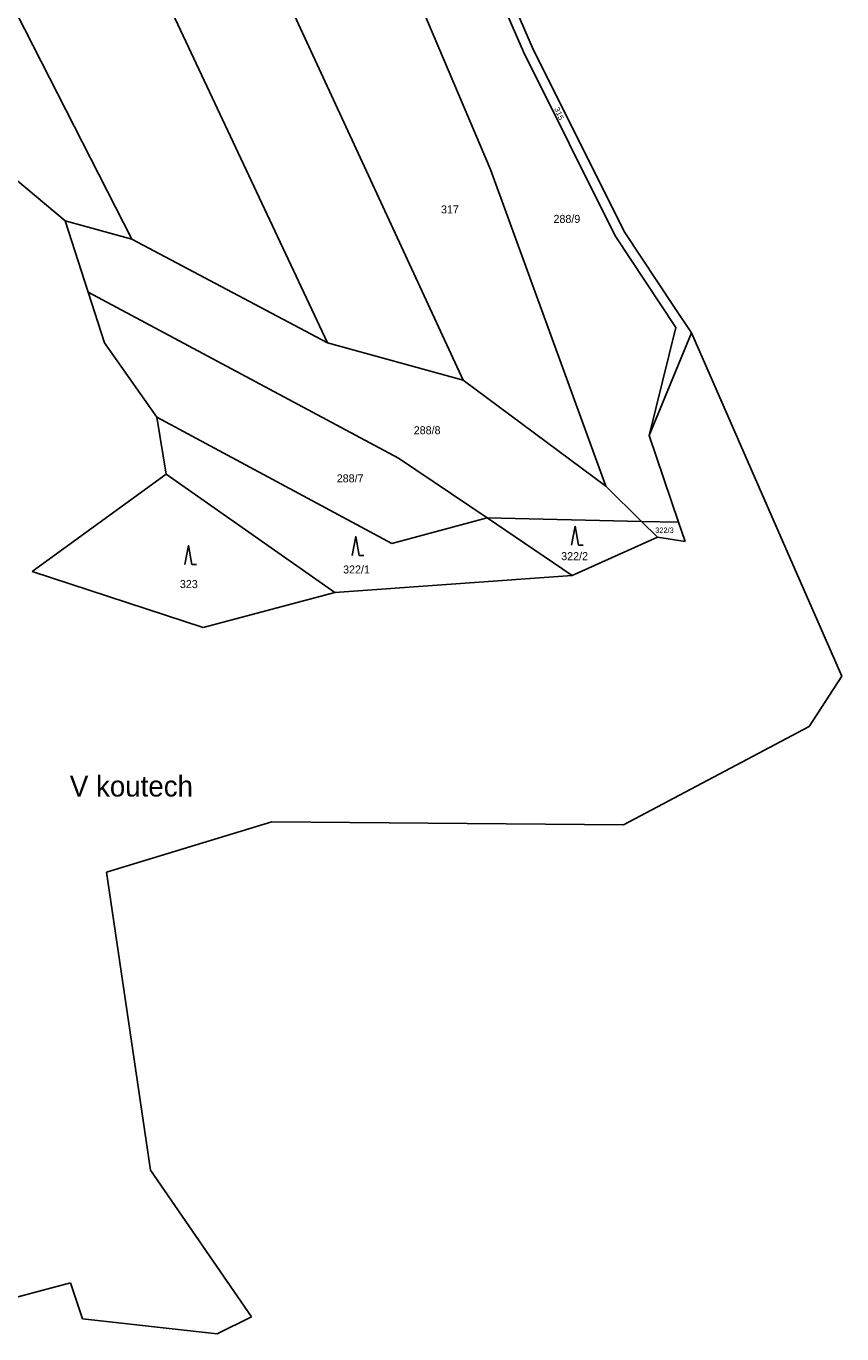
# Model space of a CAD drawing. Extents: x -664548 to -662415, y -1069720 to -1068208.
# Drawn here: x -662952.7 to -662779.3, y -1069462.9 to -1069185.2 of the extents above; entities that cross this region are included whole.
import ezdxf
from ezdxf.enums import TextEntityAlignment as Align

# ---------------------------------------------------------------- set-up
doc = ezdxf.new("R2010")
doc.units = 0
doc.header["$LTSCALE"] = 0.68
for name, color, linetype, lineweight in [('1', 7, 'Continuous', 25), ('3', 7, 'Continuous', 25), ('7', 7, 'Continuous', 13)]:
    doc.layers.add(name, color=color, linetype=linetype, lineweight=lineweight)
doc.layers.add('2', color=7, linetype='Continuous')

msp = doc.modelspace()

# ---------------------------------------------------------------- linework, layer by layer
at = {"layer": '1'}
for p, q in [((-662888.64, -1069252.46), (-662947.44, -1069127.48)), ((-662854.01, -1069215.69), (-662875.68, -1069164.53)), ((-662847.01, -1069190.67), (-662858.78, -1069163.55)), ((-662930.23, -1069230.45), (-662960.45, -1069171.24)), ((-662897.41, -1069179.04), (-662859.82, -1069260.43)), ((-662845.08, -1069189.83), (-662825.61, -1069228.81)), ((-662827.49, -1069229.75), (-662847.01, -1069190.67)), ((-662944.39, -1069226.53), (-662971.11, -1069204.3)), ((-662829.48, -1069282.94), (-662854.01, -1069215.69)), ((-662944.39, -1069226.53), (-662930.23, -1069230.45)), ((-662939.52, -1069241.68), (-662944.39, -1069226.53)), ((-662825.61, -1069228.81), (-662814.9, -1069244.97)), ((-662930.23, -1069230.45), (-662888.64, -1069252.46)), ((-662814.61, -1069249.19), (-662827.49, -1069229.75)), ((-662936.05, -1069252.46), (-662939.52, -1069241.68)), ((-662873.54, -1069276.97), (-662939.52, -1069241.68)), ((-662814.9, -1069244.97), (-662811.32, -1069250.37)), ((-662820.32, -1069272.13), (-662814.61, -1069249.19)), ((-662820.32, -1069272.13), (-662811.32, -1069250.37)), ((-662811.32, -1069250.37), (-662802.6, -1069270.24)), ((-662924.91, -1069268.24), (-662936.05, -1069252.46)), ((-662888.64, -1069252.46), (-662859.82, -1069260.43)), ((-662859.82, -1069260.43), (-662829.48, -1069282.94)), ((-662924.91, -1069268.24), (-662875, -1069295.12)), ((-662922.92, -1069280.33), (-662924.91, -1069268.24)), ((-662802.6, -1069270.24), (-662801.38, -1069273.02)), ((-662820.32, -1069272.13), (-662814.05, -1069290.58)), ((-662801.38, -1069273.02), (-662790.24, -1069298.42)), ((-662854.75, -1069289.65), (-662873.54, -1069276.97)), ((-662951.4, -1069301.06), (-662922.92, -1069280.33)), ((-662922.92, -1069280.33), (-662887.09, -1069305.47)), ((-662829.48, -1069282.94), (-662821.93, -1069290.4)), ((-662875, -1069295.12), (-662854.75, -1069289.65)), ((-662854.75, -1069289.65), (-662821.93, -1069290.4)), ((-662836.68, -1069301.85), (-662854.75, -1069289.65)), ((-662814.05, -1069290.58), (-662821.93, -1069290.4)), ((-662821.93, -1069290.4), (-662818.53, -1069293.75)), ((-662814.05, -1069290.58), (-662812.65, -1069294.69)), ((-662818.53, -1069293.75), (-662836.68, -1069301.85)), ((-662812.65, -1069294.69), (-662818.53, -1069293.75)), ((-662790.24, -1069298.42), (-662779.34, -1069323.26)), ((-662915.04, -1069312.91), (-662951.4, -1069301.06)), ((-662836.68, -1069301.85), (-662887.09, -1069305.47)), ((-662887.09, -1069305.47), (-662915.04, -1069312.91)), ((-662779.34, -1069323.26), (-662786.31, -1069333.94)), ((-662786.31, -1069333.94), (-662825.73, -1069354.84)), ((-662900.5, -1069354.16), (-662935.58, -1069364.86)), ((-662825.73, -1069354.84), (-662900.5, -1069354.16)), ((-662935.58, -1069364.86), (-662926.27, -1069428.16)), ((-662926.27, -1069428.16), (-662904.83, -1069459.34)), ((-662943.28, -1069452.09), (-662962.81, -1069457.29)), ((-662940.71, -1069459.74), (-662943.28, -1069452.09)), ((-662912.09, -1069462.92), (-662940.71, -1069459.74)), ((-662904.83, -1069459.34), (-662912.09, -1069462.92))]:
    msp.add_line(p, q, dxfattribs=at)
msp.add_lwpolyline([(-662789.89, -1069153.47), (-662857.86, -1069160.37), (-662845.08, -1069189.83)], dxfattribs=at)
at = {"layer": '3'}
for p, q in [((-662835.29, -1069295.41), (-662834.294, -1069295.41)), ((-662881.9, -1069297.62), (-662880.904, -1069297.62)), ((-662917.45, -1069299.53), (-662916.454, -1069299.53))]:
    msp.add_line(p, q, dxfattribs=at)
for points in [[(-662835.29, -1069295.41), (-662836.04, -1069291.41), (-662836.79, -1069295.41)], [(-662917.45, -1069299.53), (-662918.2, -1069295.53), (-662918.95, -1069299.53)], [(-662881.9, -1069297.62), (-662882.65, -1069293.62), (-662883.4, -1069297.62)]]:
    msp.add_lwpolyline(points, dxfattribs=at)

# ---------------------------------------------------------------- texts
at = {"layer": '2', "width": 1.1}
msp.add_text('315', height=1.14, rotation=293, dxfattribs=at).set_placement((-662840.502, -1069202.721))
at = {"layer": '2'}
for s, height, p in [('317', 1.7, (-662864.53, -1069224.985)), ('288/9', 1.7, (-662840.62, -1069227.005)), ('288/8', 1.7, (-662870.32, -1069271.885)), ('288/7', 1.7, (-662886.68, -1069282.104)), ('322/3', 1.14, (-662819, -1069292.835)), ('322/2', 1.7, (-662838.98, -1069298.625)), ('322/1', 1.7, (-662885.33, -1069301.455)), ('323', 1.7, (-662920.01, -1069304.554))]:
    msp.add_text(s, height=height, dxfattribs=at).set_placement(p)
at = {"layer": '7'}
msp.add_text('V koutech', height=4.4, dxfattribs=at).set_placement((-662930.319, -1069348.82), align=Align.CENTER)

doc.saveas('drawing.dxf')
